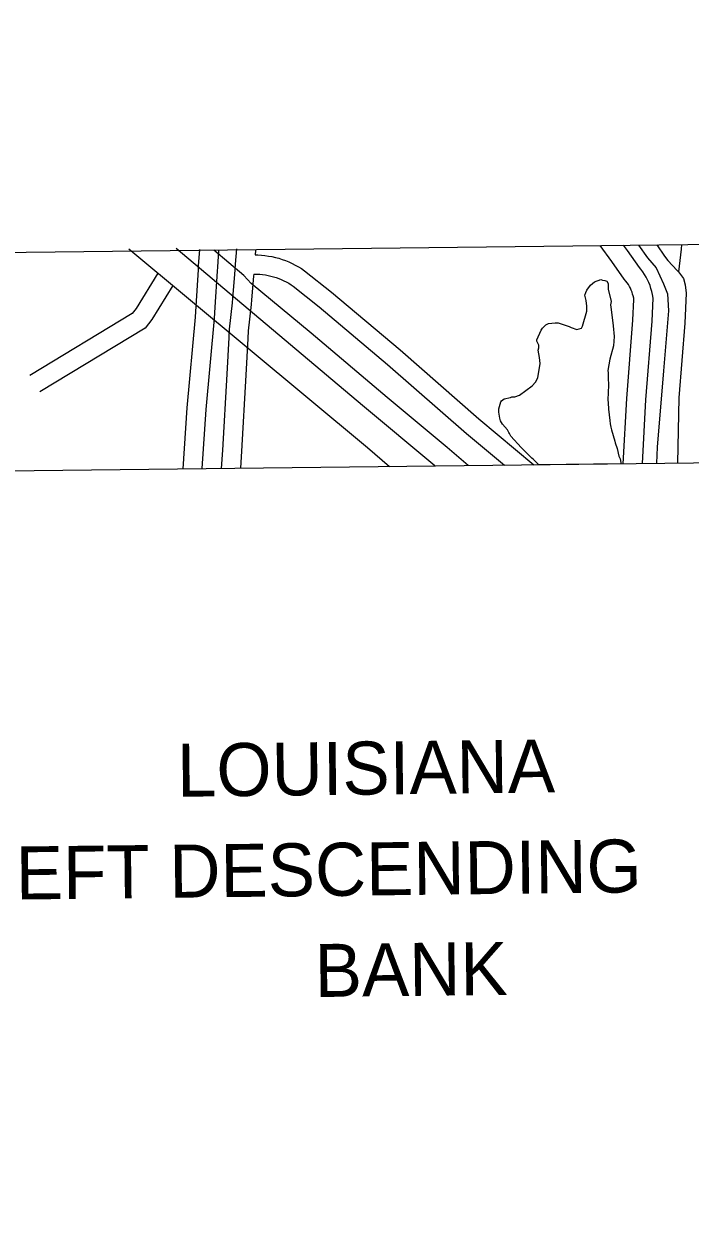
# Model space of a CAD drawing. Extents: x 3683402 to 3721514, y 487807 to 513565.
# Drawn here: x 3688424 to 3689467, y 509895 to 511772 of the extents above; entities that cross this region are included whole.
import ezdxf

# ---------------------------------------------------------------- set-up
doc = ezdxf.new("R2010")
doc.units = 0
for name, color, linetype in [('V-ANNO-SYMB', 7, 'Continuous'), ('V-GRID-FRAM', 7, 'Continuous'), ('V-RAIL-TRAK', 7, 'Continuous'), ('V-ROAD-CNTR', 7, 'Continuous'), ('V-SITE-VEGE', 7, 'Continuous'), ('V-TOPO-SHOR', 7, 'Continuous')]:
    doc.layers.add(name, color=color, linetype=linetype)

msp = doc.modelspace()

# ---------------------------------------------------------------- linework, layer by layer
at = {"layer": 'V-ANNO-SYMB'}
msp.add_lwpolyline([(3687900.3, 511066.8), (3696792.8, 511170.1), (3696858.2, 505541.9), (3687965.7, 505438.5)], close=True, dxfattribs=at)
at = {"layer": 'V-GRID-FRAM'}
msp.add_lwpolyline([(3687448, 511403.5), (3719130.8, 511772.1), (3719350.3, 493590.7), (3687651.7, 493221.8), (3687448, 511403.5)], dxfattribs=at)
at = {"layer": 'V-RAIL-TRAK'}
msp.add_lwpolyline([(3689119.5, 511081), (3689086.5, 511109.1), (3688992.7, 511187.6), (3688873.5, 511287.9), (3688779.7, 511365.8), (3688768.3, 511378.6), (3688720.9, 511418.3)], dxfattribs=at)
at = {"layer": 'V-ROAD-CNTR'}
for points in [[(3688587.8, 511420), (3688961.7, 511109.1), (3688996.4, 511079.5)], [(3689067.3, 511080.3), (3688954.2, 511174.7), (3688661.9, 511420.9)], [(3688672.9, 511075.8), (3688679.1, 511171), (3688692.2, 511313.4), (3688693.3, 511330.6), (3688696.9, 511387.2), (3688697.3, 511393.3), (3688699.1, 511419.3)], [(3688703, 511076.1), (3688709, 511168.6), (3688722.1, 511311.1), (3688723.2, 511328.7), (3688726.8, 511385.3), (3688727.2, 511391.3), (3688729, 511417.1)], [(3688756.5, 511420.1), (3688754.6, 511395.9), (3688753.3, 511379.8), (3688750.4, 511342.8), (3688749.8, 511335.7), (3688745.2, 511294.3), (3688744.5, 511281.3), (3688741.3, 511223.9), (3688734.6, 511105), (3688732.8, 511076.5)], [(3688786.5, 511417.7), (3688785.9, 511410.7)], [(3688785.9, 511410.6), (3688789.9, 511410.6), (3688795.5, 511410.2), (3688801.1, 511409.7), (3688806.6, 511408.9), (3688812.1, 511407.9), (3688817.5, 511406.7), (3688822.9, 511405.3), (3688828.2, 511403.6), (3688833.5, 511401.7), (3688838.7, 511399.6), (3688843.7, 511397.3), (3688848.7, 511394.8), (3688853.6, 511392.1), (3688858.4, 511389.1), (3688863.2, 511385.9), (3688905.2, 511352.5), (3689012.8, 511262), (3689136.2, 511154.1), (3689222.6, 511082.1)], [(3689362.3, 511083.8), (3689367.9, 511185.7), (3689377.5, 511308.7), (3689379.1, 511341), (3689378.8, 511343.1), (3689378.1, 511346.3), (3689377.2, 511349.4), (3689376.2, 511352.5), (3689375, 511355.5), (3689373.6, 511358.4), (3689372.1, 511361.3), (3689370.5, 511364.1), (3689368.6, 511366.8), (3689366.7, 511369.4), (3689363.9, 511372.7), (3689344.7, 511400.1), (3689326.3, 511425.3)], [(3689392.4, 511084.1), (3689397.9, 511183.7), (3689407.5, 511306.8), (3689409.2, 511342.7), (3689408.3, 511348.7), (3689407.2, 511353.5), (3689405.9, 511358.2), (3689404.4, 511362.8), (3689402.6, 511367.3), (3689400.6, 511371.7), (3689398.3, 511376), (3689395.8, 511380.2), (3689393.1, 511384.2), (3689390.1, 511388.1), (3689387.7, 511391), (3689369.1, 511417.6), (3689363.1, 511425.8)], [(3688633.5, 511382.1), (3688599.4, 511326.7), (3688593.2, 511318.7), (3688433, 511221.7)], [(3688783.5, 511380.6), (3688783.2, 511377.4), (3688780.3, 511340.4), (3688779.7, 511332.9), (3688775.1, 511291.8), (3688774.4, 511279.6), (3688771.2, 511222.2), (3688764.5, 511103.2), (3688762.9, 511076.8)], [(3688783.5, 511380.6), (3688784.5, 511380.6), (3688788.8, 511380.6), (3688793.2, 511380.3), (3688797.5, 511379.9), (3688801.8, 511379.3), (3688806.1, 511378.5), (3688810.3, 511377.6), (3688814.5, 511376.4), (3688818.7, 511375.1), (3688822.8, 511373.7), (3688826.8, 511372), (3688830.8, 511370.2), (3688834.6, 511368.3), (3688838.4, 511366.2), (3688842.2, 511363.9), (3688845.5, 511361.6), (3688886.2, 511329.3), (3688993.3, 511239.2), (3689116.7, 511131.3), (3689176.4, 511081.6)], [(3688656.8, 511362.7), (3688624.1, 511309.7), (3688613.6, 511295.9), (3688448.6, 511196.1)]]:
    msp.add_lwpolyline(points, dxfattribs=at)
at = {"layer": 'V-SITE-VEGE'}
for p, q in [((3689317.4, 511368.7), (3689327.3, 511372.2)), ((3689327.3, 511372.2), (3689330.1, 511371)), ((3689303.6, 511351.9), (3689305.4, 511355.4)), ((3689305.4, 511355.4), (3689311.1, 511363.5)), ((3689311.1, 511363.5), (3689317.4, 511368.7)), ((3689330.1, 511371), (3689333.6, 511370.5)), ((3689333.6, 511370.5), (3689336.5, 511369.3)), ((3689336.5, 511369.3), (3689338.8, 511365.9)), ((3689338.8, 511365.9), (3689338.8, 511357.2)), ((3689338.8, 511357.2), (3689343.5, 511337.6)), ((3689302.5, 511347.8), (3689303.6, 511351.9)), ((3689304.2, 511339.2), (3689302.5, 511347.8)), ((3689305.4, 511330.5), (3689304.2, 511339.2)), ((3689343.5, 511337.6), (3689342.4, 511332.4)), ((3689298.6, 511299.3), (3689305.5, 511322.4)), ((3689305.5, 511322.4), (3689305.4, 511330.5)), ((3689342.4, 511332.4), (3689343.6, 511325.4)), ((3689343.6, 511325.4), (3689346.5, 511299.5)), ((3689235.7, 511295.7), (3689241.4, 511300.9)), ((3689241.4, 511300.9), (3689245.5, 511303.2)), ((3689245.5, 511303.2), (3689255.8, 511304.4)), ((3689255.8, 511304.4), (3689260.5, 511304.4)), ((3689260.5, 511304.4), (3689265.1, 511302.7)), ((3689265.1, 511302.7), (3689277.8, 511298.7)), ((3689277.8, 511298.7), (3689280.7, 511297)), ((3689280.7, 511297), (3689289.9, 511294.1)), ((3689296.9, 511295.9), (3689298.6, 511299.3)), ((3689346.5, 511299.5), (3689348.3, 511282.7)), ((3689227, 511277.8), (3689233.9, 511292.8)), ((3689233.9, 511292.8), (3689235.7, 511295.7)), ((3689289.9, 511294.1), (3689296.9, 511295.9)), ((3689348.3, 511282.7), (3689347.2, 511268.3)), ((3689227, 511275.4), (3689227, 511277.8)), ((3689230, 511269.1), (3689227, 511275.4)), ((3689229.4, 511261.6), (3689230, 511265.1)), ((3689231.2, 511250), (3689229.4, 511261.6)), ((3689230, 511265.1), (3689230, 511269.1)), ((3689347.2, 511268.3), (3689341.5, 511247.5)), ((3689228.9, 511218.3), (3689232.3, 511240.8)), ((3689232.3, 511240.8), (3689231.2, 511250)), ((3689341.5, 511247.5), (3689338.1, 511229.6)), ((3689338.1, 511229.6), (3689338.6, 511226.1)), ((3689338.6, 511226.1), (3689338.7, 511218)), ((3689200.1, 511191.1), (3689219.7, 511205.5)), ((3689219.7, 511205.5), (3689224.9, 511211.3)), ((3689224.9, 511211.3), (3689228.9, 511218.3)), ((3689339.3, 511206.5), (3689338.2, 511183.9)), ((3689338.7, 511218), (3689339.3, 511206.5)), ((3689171.9, 511182.3), (3689175.9, 511185.2)), ((3689175.9, 511185.2), (3689185.7, 511187.5)), ((3689185.7, 511187.5), (3689188, 511188.7)), ((3689188, 511188.7), (3689192.6, 511188.7)), ((3689192.6, 511188.7), (3689200.1, 511191.1)), ((3689167.3, 511169.6), (3689170.7, 511180.6)), ((3689167.3, 511164.4), (3689167.3, 511169.6)), ((3689170.7, 511180.6), (3689171.9, 511182.3)), ((3689338.2, 511183.9), (3689338.8, 511179.3)), ((3689338.8, 511179.3), (3689339.4, 511168.9)), ((3689339.4, 511168.9), (3689341.2, 511151.6)), ((3689169.1, 511155.2), (3689167.3, 511164.4)), ((3689170.2, 511151.1), (3689169.1, 511155.2)), ((3689173.1, 511145.9), (3689170.2, 511151.1)), ((3689341.2, 511151.6), (3689341.8, 511146.4)), ((3689181.2, 511136.7), (3689173.1, 511145.9)), ((3689183, 511132.7), (3689181.2, 511136.7)), ((3689184.2, 511130.9), (3689183, 511132.7)), ((3689186.5, 511126.9), (3689184.2, 511130.9)), ((3689341.8, 511146.4), (3689342.9, 511141.2)), ((3689342.9, 511141.2), (3689344.1, 511136.6)), ((3689344.1, 511136.6), (3689349.3, 511119.3)), ((3689202.7, 511109.1), (3689186.5, 511126.9)), ((3689214.9, 511096.4), (3689202.7, 511109.1)), ((3689349.3, 511119.3), (3689349.9, 511116.4)), ((3689349.9, 511116.4), (3689352.8, 511107.8)), ((3689219.5, 511092.4), (3689214.9, 511096.4)), ((3689221.8, 511090.1), (3689219.5, 511092.4)), ((3689352.8, 511107.8), (3689355.8, 511095.6)), ((3689355.8, 511095.6), (3689357.5, 511091.6)), ((3689357.5, 511091.6), (3689358.7, 511085.8)), ((3689230.2, 511082.2), (3689221.8, 511090.1)), ((3689358.9, 511083.7), (3689230.2, 511082.2)), ((3689358.7, 511085.8), (3689358.9, 511083.7))]:
    msp.add_line(p, q, dxfattribs=at)
at = {"layer": 'V-TOPO-SHOR'}
for points in [[(3689386.2, 511426), (3689400.4, 511406), (3689414, 511390.2), (3689425.3, 511365.5), (3689431.8, 511349.6), (3689433.1, 511323.2), (3689425.7, 511229), (3689415.5, 511109.5), (3689414.8, 511084.4)], [(3689415, 511426.4), (3689426.9, 511408.5), (3689432.2, 511402), (3689447, 511386.2), (3689448.8, 511384), (3689457, 511373.8), (3689459.4, 511363.8), (3689461.2, 511350.9), (3689459, 511303.8), (3689449.4, 511186.7), (3689447.6, 511084.8)], [(3689453.8, 511426.8), (3689453.3, 511419.7), (3689448.8, 511384)]]:
    msp.add_lwpolyline(points, dxfattribs=at)

# ---------------------------------------------------------------- texts
at = {"layer": 'V-ANNO-SYMB'}
for s, p in [('LOUISIANA', (3688663.9, 510562.3)), ('LEFT DESCENDING ', (3688349.6, 510400.7)), ('BANK', (3688879.5, 510248.8))]:
    msp.add_text(s, height=83, rotation=0.666, dxfattribs=at).set_placement(p)

doc.saveas('drawing.dxf')
